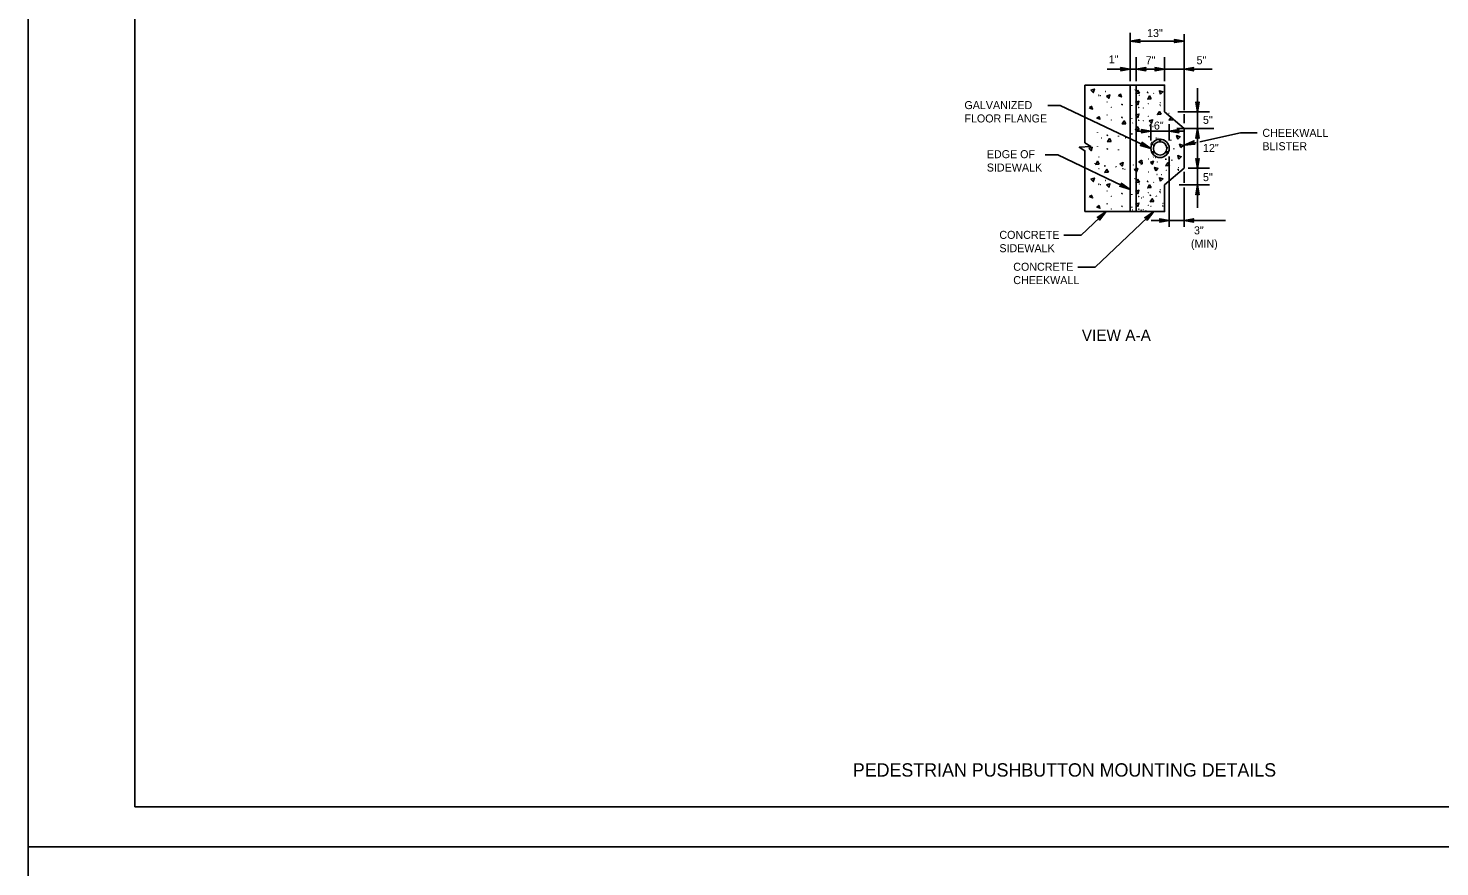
# Model space of a CAD drawing. Extents: x 36 to 940, y -1166 to 1210.
# Drawn here: x 36 to 565, y -579 to -265 of the extents above; entities that cross this region are included whole.
import ezdxf

# ---------------------------------------------------------------- set-up
doc = ezdxf.new("R2010")
doc.units = 0
for name, color, linetype in [('1', 7, 'Continuous'), ('2', 7, 'Continuous'), ('Default', 7, 'Continuous'), ('PLT-BNDY', 7, 'Continuous')]:
    doc.layers.add(name, color=color, linetype=linetype)

msp = doc.modelspace()

# ---------------------------------------------------------------- linework, layer by layer
at = {"layer": '1'}
for p, q in [((75.86, 7.17), (75.86, -556.83)), ((448.81, -284.84), (448.81, -266.77)), ((468.98, -295.74), (468.98, -267.18)), ((448.81, -269.8), (469.03, -269.8)), ((440.17, -280.34), (479.52, -280.34)), ((451.08, -284.84), (451.08, -275.83)), ((461.7, -284.84), (461.7, -275.83)), ((474.04, -332.3), (474.04, -287.49)), ((417.93, -293.9), (422.58, -293.9)), ((422.58, -293.9), (456.58, -310.03)), ((456.58, -307.08), (456.58, -300.82)), ((463.44, -307.08), (463.44, -300.92)), ((478.55, -296.32), (466.62, -296.32)), ((468.98, -300.61), (468.98, -297.14)), ((451.3, -303.58), (468.71, -303.58)), ((478.55, -302.58), (470.52, -302.58)), ((490.1, -304.15), (474.87, -307.51)), ((496.4, -304.15), (490.1, -304.15)), ((473.57, -307.8), (469.01, -308.8)), ((417, -312.45), (421.66, -312.45)), ((421.66, -312.45), (448.81, -325.38)), ((463.44, -313.08), (463.44, -339.49)), ((469.01, -318.83), (469.01, -322.97)), ((478.55, -317.49), (470.52, -317.49)), ((478.55, -323.74), (467.12, -323.74)), ((469.01, -324.63), (469.01, -339.49)), ((430.44, -342.54), (439.82, -333.7)), ((435.63, -354.5), (457.66, -333.74)), ((456.64, -337.06), (484.51, -337.06)), ((423.93, -342.54), (430.44, -342.54)), ((429.13, -354.5), (435.63, -354.5)), ((861.86, -556.83), (75.86, -556.83)), ((75.86, -556.83), (661.86, -556.83))]:
    msp.add_line(p, q, dxfattribs=at)
for points in [[(452.27, -270.23), (452.14, -269.98), (448.81, -269.8), (452.27, -270.23), (452.44, -270.38), (448.81, -269.8), (452.13, -269.63), (452.26, -269.39), (448.81, -269.8), (452.44, -269.22), (452.26, -269.39)], [(465.58, -270.23), (465.71, -269.98), (469.03, -269.8), (465.58, -270.23), (465.4, -270.38), (469.03, -269.8), (465.71, -269.63), (465.59, -269.39), (469.03, -269.8), (465.4, -269.22), (465.59, -269.39)], [(445.36, -279.9), (445.49, -280.15), (448.81, -280.34), (445.36, -279.9), (445.18, -279.75), (448.81, -280.34), (445.49, -280.5), (445.37, -280.75), (448.81, -280.34), (445.18, -280.91), (445.37, -280.75)], [(454.53, -280.77), (454.4, -280.52), (451.08, -280.34), (454.53, -280.77), (454.71, -280.92), (451.08, -280.34), (454.4, -280.17), (454.52, -279.93), (451.08, -280.34), (454.71, -279.76), (454.52, -279.93)], [(458.27, -280.77), (458.4, -280.52), (461.72, -280.34), (458.27, -280.77), (458.09, -280.92), (461.72, -280.34), (458.4, -280.17), (458.28, -279.93), (461.72, -280.34), (458.09, -279.76), (458.28, -279.93)], [(472.46, -280.77), (472.33, -280.52), (469.01, -280.34), (472.46, -280.77), (472.64, -280.92), (469.01, -280.34), (472.33, -280.17), (472.45, -279.93), (469.01, -280.34), (472.64, -279.76), (472.45, -279.93)], [(434.12, -288.24), (435.42, -287.81), (434.98, -289.1), (434.12, -288.24)], [(434.12, -288.24), (435.42, -287.81), (434.98, -289.1), (434.12, -288.24)], [(439.95, -290.39), (441.24, -289.96), (440.81, -291.25), (439.95, -290.39)], [(452.34, -289.34), (450.98, -289.45), (451.7, -288.29), (452.34, -289.34)], [(456.73, -291.41), (455.37, -291.52), (456.1, -290.37), (456.73, -291.41)], [(456.73, -291.41), (455.37, -291.52), (456.1, -290.37), (456.73, -291.41)], [(460.22, -289.73), (459.79, -288.44), (461.09, -288.87), (460.22, -289.73)], [(450.81, -292.79), (452.1, -292.36), (451.67, -293.66), (450.81, -292.79)], [(450.81, -292.79), (452.1, -292.36), (451.67, -293.66), (450.81, -292.79)], [(460.38, -297.24), (459.02, -297.35), (459.74, -296.2), (460.38, -297.24)], [(474.48, -292.84), (474.23, -292.97), (474.04, -296.3), (474.48, -292.84), (474.63, -292.67), (474.04, -296.3), (473.88, -292.98), (473.63, -292.85), (474.04, -296.3), (473.47, -292.67), (473.63, -292.85)], [(447.19, -300.77), (445.83, -300.88), (446.56, -299.72), (447.19, -300.77)], [(447.19, -300.77), (445.83, -300.88), (446.56, -299.72), (447.19, -300.77)], [(450.81, -297.6), (452.1, -297.17), (451.67, -298.46), (450.81, -297.6)], [(450.81, -297.6), (452.1, -297.17), (451.67, -298.46), (450.81, -297.6)], [(455.9, -299.74), (457.19, -299.31), (456.76, -300.61), (455.9, -299.74)], [(464.77, -299.31), (463.41, -299.42), (464.14, -298.27), (464.77, -299.31)], [(441.69, -307.43), (440.33, -307.54), (441.06, -306.38), (441.69, -307.43)], [(441.69, -307.43), (440.33, -307.54), (441.06, -306.38), (441.69, -307.43)], [(452.15, -302.96), (450.79, -303.07), (451.51, -301.91), (452.15, -302.96)], [(452.15, -302.96), (450.79, -303.07), (451.51, -301.91), (452.15, -302.96)], [(453.13, -303.15), (453.26, -303.4), (456.58, -303.58), (453.13, -303.15), (452.95, -303), (456.58, -303.58), (453.26, -303.75), (453.14, -303.99), (456.58, -303.58), (452.95, -304.16), (453.14, -303.99)], [(466.89, -303.15), (466.76, -303.4), (463.44, -303.58), (466.89, -303.15), (467.07, -303), (463.44, -303.58), (466.76, -303.75), (466.88, -303.99), (463.44, -303.58), (467.07, -304.16), (466.88, -303.99)], [(466.63, -306.51), (466.2, -305.21), (467.5, -305.64), (466.63, -306.51)], [(473.61, -306.03), (473.86, -305.9), (474.04, -302.58), (473.61, -306.03), (473.46, -306.21), (474.04, -302.58), (474.21, -305.9), (474.45, -306.02), (474.04, -302.58), (474.62, -306.21), (474.45, -306.02)], [(433.27, -310.03), (434.57, -309.6), (434.14, -310.89), (433.27, -310.03)], [(453.33, -307.97), (453.34, -308.28), (456.58, -310.03), (453.33, -307.97), (453.22, -307.73), (456.58, -310.03), (453.18, -308.63), (452.94, -308.82), (456.58, -310.03), (452.67, -308.9), (452.94, -308.82)], [(467.78, -309.75), (467.35, -308.46), (468.65, -308.89), (467.78, -309.75)], [(472.59, -307.39), (472.52, -307.7), (469.01, -308.8), (472.59, -307.39), (472.74, -307.18), (469.01, -308.8), (472.62, -308.07), (472.81, -308.3), (469.01, -308.8), (473.06, -308.43), (472.81, -308.3)], [(437.24, -315.91), (435.88, -316.03), (436.6, -314.87), (437.24, -315.91)], [(444.89, -315.8), (446.19, -315.37), (445.75, -316.66), (444.89, -315.8)], [(444.89, -315.8), (446.19, -315.37), (445.75, -316.66), (444.89, -315.8)], [(453.16, -314.47), (453.27, -315.82), (452.11, -315.1), (453.16, -314.47)], [(458.36, -318.43), (457.93, -317.13), (459.22, -317.57), (458.36, -318.43)], [(463.57, -316.47), (462.2, -316.58), (462.93, -315.43), (463.57, -316.47)], [(463.57, -316.47), (462.2, -316.58), (462.93, -315.43), (463.57, -316.47)], [(467.06, -314.05), (466.63, -312.75), (467.92, -313.18), (467.06, -314.05)], [(473.61, -314.04), (473.86, -314.16), (474.04, -317.49), (473.61, -314.04), (473.46, -313.86), (474.04, -317.49), (474.21, -314.17), (474.45, -314.04), (474.04, -317.49), (474.62, -313.86), (474.45, -314.04)], [(434.12, -321.58), (435.42, -321.15), (434.98, -322.45), (434.12, -321.58)], [(434.12, -321.58), (435.42, -321.15), (434.98, -322.45), (434.12, -321.58)], [(440.72, -318.97), (439.36, -319.08), (440.09, -317.93), (440.72, -318.97)], [(440.72, -318.97), (439.36, -319.08), (440.09, -317.93), (440.72, -318.97)], [(450.33, -317.95), (451.62, -317.52), (451.19, -318.81), (450.33, -317.95)], [(452.34, -322.68), (450.98, -322.79), (451.7, -321.64), (452.34, -322.68)], [(460.22, -322.33), (459.79, -321.04), (461.09, -321.47), (460.22, -322.33)], [(439.95, -323.73), (441.24, -323.3), (440.81, -324.59), (439.95, -323.73)], [(445.56, -323.32), (445.57, -323.63), (448.81, -325.38), (445.56, -323.32), (445.45, -323.08), (448.81, -325.38), (445.41, -323.98), (445.17, -324.17), (448.81, -325.38), (444.9, -324.25), (445.17, -324.17)], [(450.81, -326.14), (452.1, -325.71), (451.67, -327), (450.81, -326.14)], [(450.81, -326.14), (452.1, -325.71), (451.67, -327), (450.81, -326.14)], [(456.73, -324.75), (455.37, -324.86), (456.1, -323.71), (456.73, -324.75)], [(456.73, -324.75), (455.37, -324.86), (456.1, -323.71), (456.73, -324.75)], [(474.48, -327.22), (474.23, -327.09), (474.04, -323.77), (474.48, -327.22), (474.63, -327.4), (474.04, -323.77), (473.88, -327.09), (473.63, -327.21), (474.04, -323.77), (473.47, -327.4), (473.63, -327.21)], [(450.81, -330.94), (452.1, -330.51), (451.67, -331.8), (450.81, -330.94)], [(450.81, -330.94), (452.1, -330.51), (451.67, -331.8), (450.81, -330.94)], [(457.71, -329.93), (456.35, -330.04), (457.08, -328.89), (457.71, -329.93)], [(457.71, -329.93), (456.35, -330.04), (457.08, -328.89), (457.71, -329.93)], [(437.35, -336.66), (437.26, -336.36), (439.82, -333.7), (437.35, -336.66), (437.32, -336.92), (439.82, -333.7), (437, -336.08), (436.72, -335.97), (439.82, -333.7), (436.44, -335.98), (436.72, -335.97)], [(455.19, -336.71), (455.11, -336.41), (457.66, -333.74), (455.19, -336.71), (455.16, -336.96), (457.66, -333.74), (454.85, -336.12), (454.56, -336.01), (457.66, -333.74), (454.29, -336.02), (454.56, -336.01)], [(459.99, -336.62), (460.11, -336.87), (463.44, -337.06), (459.99, -336.62), (459.81, -336.47), (463.44, -337.06), (460.12, -337.22), (459.99, -337.47), (463.44, -337.06), (459.81, -337.63), (459.99, -337.47)], [(472.46, -336.62), (472.33, -336.87), (469.01, -337.06), (472.46, -336.62), (472.64, -336.47), (469.01, -337.06), (472.33, -337.22), (472.45, -337.47), (469.01, -337.06), (472.64, -337.63), (472.45, -337.47)]]:
    msp.add_lwpolyline(points, dxfattribs=at)
for centre in [(437.78, -290.3), (439.62, -288.69), (439.62, -288.69), (452.18, -290.08), (452.18, -290.08), (455.33, -288.95), (441.74, -294.64), (441.74, -294.64), (445.8, -293.51), (453.73, -294.85), (455.57, -293.24), (455.57, -293.24), (460.14, -292.89), (460.13, -293.99), (460.13, -293.99), (441.74, -299.44), (441.74, -299.44), (445.8, -298.31), (453.73, -299.66), (455.57, -298.05), (455.57, -298.05), (463.37, -296.85), (438.13, -306.1), (438.13, -306.1), (440.3, -304.97), (449.3, -304.66), (450.97, -304.71), (450.97, -304.71), (455.72, -305.64), (457.36, -301.84), (459.28, -306.32), (440.3, -310.09), (456.85, -307.8), (456.85, -307.8), (457.36, -308.59), (460.87, -307.8), (460.87, -307.8), (462.45, -309.83), (462.45, -309.83), (463.55, -309.84), (437.16, -313.24), (437.16, -313.24), (439.32, -316.51), (450, -316.25), (450, -316.25), (455.71, -314.04), (458.31, -313.46), (459.01, -315.14), (459.01, -315.14), (462.17, -314.01), (466.97, -317.2), (437.16, -317.64), (437.16, -317.64), (439.62, -322.03), (439.62, -322.03), (446.83, -317.86), (455.33, -322.29), (455.71, -318.84), (460.57, -319.91), (462.41, -318.3), (462.41, -318.3), (466.97, -318.3), (466.97, -318.3), (437.78, -323.64), (445.8, -326.85), (452.18, -323.42), (452.18, -323.42), (455.57, -326.59), (455.57, -326.59), (456.32, -327.47), (460.14, -325.48), (460.13, -326.59), (460.13, -326.59), (441.74, -327.98), (441.74, -327.98), (441.74, -332.78), (441.74, -332.78), (445.8, -331.65), (453.16, -328.6), (453.16, -328.6), (453.73, -328.2), (453.73, -333), (455.57, -331.39), (455.57, -331.39), (456.56, -331.77), (456.56, -331.77), (461.12, -331.76), (461.12, -331.76), (461.12, -330.66), (454.72, -333.37)]:
    msp.add_circle(centre, 0.00223, dxfattribs=at)
at = {"layer": '2'}
msp.add_line((480.1, -302.58), (466.25, -302.58), dxfattribs=at)
at = {"layer": 'Default'}
for p, q in [((436.95, -290.11), (437.02, -290.04)), ((437.13, -290.18), (436.95, -290.14)), ((437.02, -290.04), (437.13, -290.18)), ((448.81, -286.32), (448.81, -333.74)), ((450.59, -288.17), (450.62, -288.03)), ((451.08, -286.32), (451.08, -333.74)), ((455.27, -289.29), (455.38, -288.93)), ((457.64, -289.5), (457.6, -289.29)), ((440.15, -292.73), (440.19, -292.59)), ((445.74, -293.85), (445.85, -293.49)), ((449.43, -294.06), (449.39, -293.85)), ((451.92, -294.66), (451.99, -294.59)), ((452.1, -294.74), (451.92, -294.7)), ((451.99, -294.59), (452.1, -294.74)), ((459.87, -293.64), (460.02, -293.53)), ((459.95, -293.71), (459.87, -293.64)), ((460.02, -293.53), (459.98, -293.71)), ((440.15, -297.53), (440.19, -297.39)), ((445.74, -298.65), (445.85, -298.29)), ((449.43, -298.86), (449.39, -298.65)), ((449.86, -300.47), (449.64, -300.51)), ((451.92, -299.47), (451.99, -299.39)), ((452.1, -299.54), (451.92, -299.5)), ((451.99, -299.39), (452.1, -299.54)), ((456.28, -301.44), (456.06, -301.48)), ((436.53, -304.19), (436.57, -304.05)), ((440.24, -305.31), (440.35, -304.95)), ((444.49, -305.52), (444.45, -305.31)), ((446.98, -306.13), (447.05, -306.05)), ((447.05, -306.05), (447.15, -306.2)), ((449.64, -304.72), (449.28, -304.61)), ((456.06, -305.69), (455.7, -305.59)), ((456.71, -301.73), (456.53, -301.69)), ((458.63, -306.2), (458.45, -306.16)), ((469.01, -302.58), (469.01, -310.03)), ((436.53, -309.32), (436.57, -309.17)), ((440.24, -310.43), (440.35, -310.07)), ((444.49, -310.65), (444.45, -310.43)), ((456.53, -308.4), (456.6, -308.33)), ((456.71, -308.48), (456.53, -308.44)), ((456.6, -308.33), (456.71, -308.48)), ((462.72, -309.65), (462.8, -309.58)), ((462.9, -309.72), (462.72, -309.68)), ((462.8, -309.58), (462.9, -309.72)), ((464.05, -307.02), (464.01, -306.81)), ((465.2, -310.27), (465.16, -310.05)), ((469.01, -317.49), (469.01, -310.03)), ((435.56, -315.74), (435.6, -315.59)), ((439.27, -316.85), (439.37, -316.49)), ((443.52, -317.07), (443.48, -316.85)), ((452.98, -316.14), (452.84, -316.1)), ((457.48, -313.27), (457.55, -313.2)), ((462.11, -314.35), (462.22, -313.99)), ((464.47, -314.56), (464.44, -314.35)), ((446, -317.67), (446.08, -317.6)), ((446.18, -317.74), (446, -317.71)), ((446.08, -317.6), (446.18, -317.74)), ((450.59, -321.52), (450.62, -321.37)), ((451.41, -318.05), (451.37, -317.84)), ((455.27, -322.63), (455.38, -322.27)), ((457.64, -322.85), (457.6, -322.63)), ((458.75, -319.72), (458.82, -319.65)), ((458.93, -319.8), (458.75, -319.76)), ((458.82, -319.65), (458.93, -319.8)), ((466.71, -317.96), (466.85, -317.85)), ((466.78, -318.03), (466.71, -317.96)), ((466.85, -317.85), (466.82, -318.03)), ((436.95, -323.45), (437.02, -323.38)), ((437.13, -323.52), (436.95, -323.49)), ((437.02, -323.38), (437.13, -323.52)), ((440.15, -326.07), (440.19, -325.93)), ((445.74, -327.19), (445.85, -326.83)), ((449.43, -327.4), (449.39, -327.19)), ((451.92, -328.01), (451.99, -327.94)), ((451.99, -327.94), (452.1, -328.08)), ((456.26, -327.81), (456.37, -327.45)), ((458.62, -328.02), (458.59, -327.81)), ((459.87, -326.24), (460.02, -326.13)), ((459.95, -326.31), (459.87, -326.24)), ((460.02, -326.13), (459.98, -326.31)), ((440.15, -330.88), (440.19, -330.73)), ((445.74, -331.99), (445.85, -331.63)), ((449.43, -332.2), (449.39, -331.99)), ((449.86, -333.07), (449.64, -333.11)), ((452.1, -328.08), (451.92, -328.04)), ((451.92, -332.81), (451.99, -332.74)), ((452.1, -332.88), (451.92, -332.84)), ((451.99, -332.74), (452.1, -332.88)), ((452.9, -333.18), (452.97, -333.11)), ((453.08, -333.26), (452.9, -333.22)), ((452.97, -333.11), (453.08, -333.26)), ((460.86, -331.42), (461, -331.31)), ((460.93, -331.49), (460.86, -331.42)), ((461, -331.31), (460.97, -331.49))]:
    msp.add_line(p, q, dxfattribs=at)
for points in [[(431.83, -286.32), (431.83, -307.93), (434.03, -309.33), (429.72, -309.61), (431.83, -310.9), (431.83, -333.74)], [(431.83, -286.32), (461.72, -286.32), (461.72, -296.32), (469.01, -302.58)], [(444.3, -290.22), (445.52, -290.72), (445.2, -289.75), (444.45, -290.15)], [(433.48, -294.78), (434.69, -295.28), (434.37, -294.31), (433.62, -294.7)], [(436.24, -298.62), (437.46, -299.12), (437.14, -298.15), (436.38, -298.54)], [(456.99, -316.07), (457.49, -314.85), (456.53, -315.17), (456.92, -315.93)], [(431.83, -333.74), (461.72, -333.74), (461.72, -323.74), (469.01, -317.49)], [(433.48, -328.12), (434.69, -328.62), (434.37, -327.65), (433.62, -328.05)], [(436.24, -331.96), (437.46, -332.46), (437.14, -331.49), (436.38, -331.89)]]:
    msp.add_lwpolyline(points, dxfattribs=at)
for points in [[(459.8, -306.6), (460.22, -306.6), (460.22, -307.51), (459.8, -307.51)], [(457.15, -311.93), (456.93, -311.56), (457.72, -311.11), (457.93, -311.47)], [(463.08, -311.57), (462.87, -311.93), (462.08, -311.48), (462.29, -311.11)]]:
    msp.add_lwpolyline(points, close=True, dxfattribs=at)
for radius in [3.43, 2.52]:
    msp.add_circle((460.01, -310.03), radius, dxfattribs=at)
at = {"layer": 'PLT-BNDY'}
for points in [[(35.86, 22.17), (876.86, 22.17), (876.86, -571.83), (35.86, -571.83)], [(35.86, -571.83), (876.86, -571.83), (876.86, -1165.83), (35.86, -1165.83)]]:
    msp.add_lwpolyline(points, close=True, dxfattribs=at)

# ---------------------------------------------------------------- texts
at = {"layer": '2'}
for s, height, p in [('13"', 3, (455.14, -268.29)), ('1"', 3, (440.78, -278.14)), ('7"', 3, (454.61, -278.49)), ('5"', 3, (473.69, -278.49)), ('GALVANIZED', 3, (386.69, -295.3)), ('FLOOR FLANGE', 3, (386.69, -300.3)), ('6"', 3, (457.7, -302.97)), ('5"', 3, (476.09, -300.83)), ('CHEEKWALL', 3, (498.36, -305.71)), ('EDGE OF', 3, (395.09, -313.7)), ('12"', 3, (476.09, -311.36)), ('BLISTER', 3, (498.36, -310.71)), ('SIDEWALK', 3, (395.09, -318.7)), ('5"', 3, (476.09, -322.3)), ('CONCRETE', 3, (399.79, -343.94)), (' 3"', 3, (471.59, -342.24)), ('SIDEWALK', 3, (399.79, -348.94)), ('(MIN)', 3, (471.59, -347.24)), ('CONCRETE', 3, (404.99, -355.9)), ('CHEEKWALL', 3, (404.99, -360.9)), ('VIEW A-A', 4.3, (430.68, -382.22)), ('PEDESTRIAN PUSHBUTTON MOUNTING DETAILS', 5, (344.87, -545.53))]:
    msp.add_text(s, height=height, dxfattribs=at).set_placement(p)

doc.saveas('drawing.dxf')
